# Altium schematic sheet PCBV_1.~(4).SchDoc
size A4; SheetNumber: 1; SheetTotal: 1
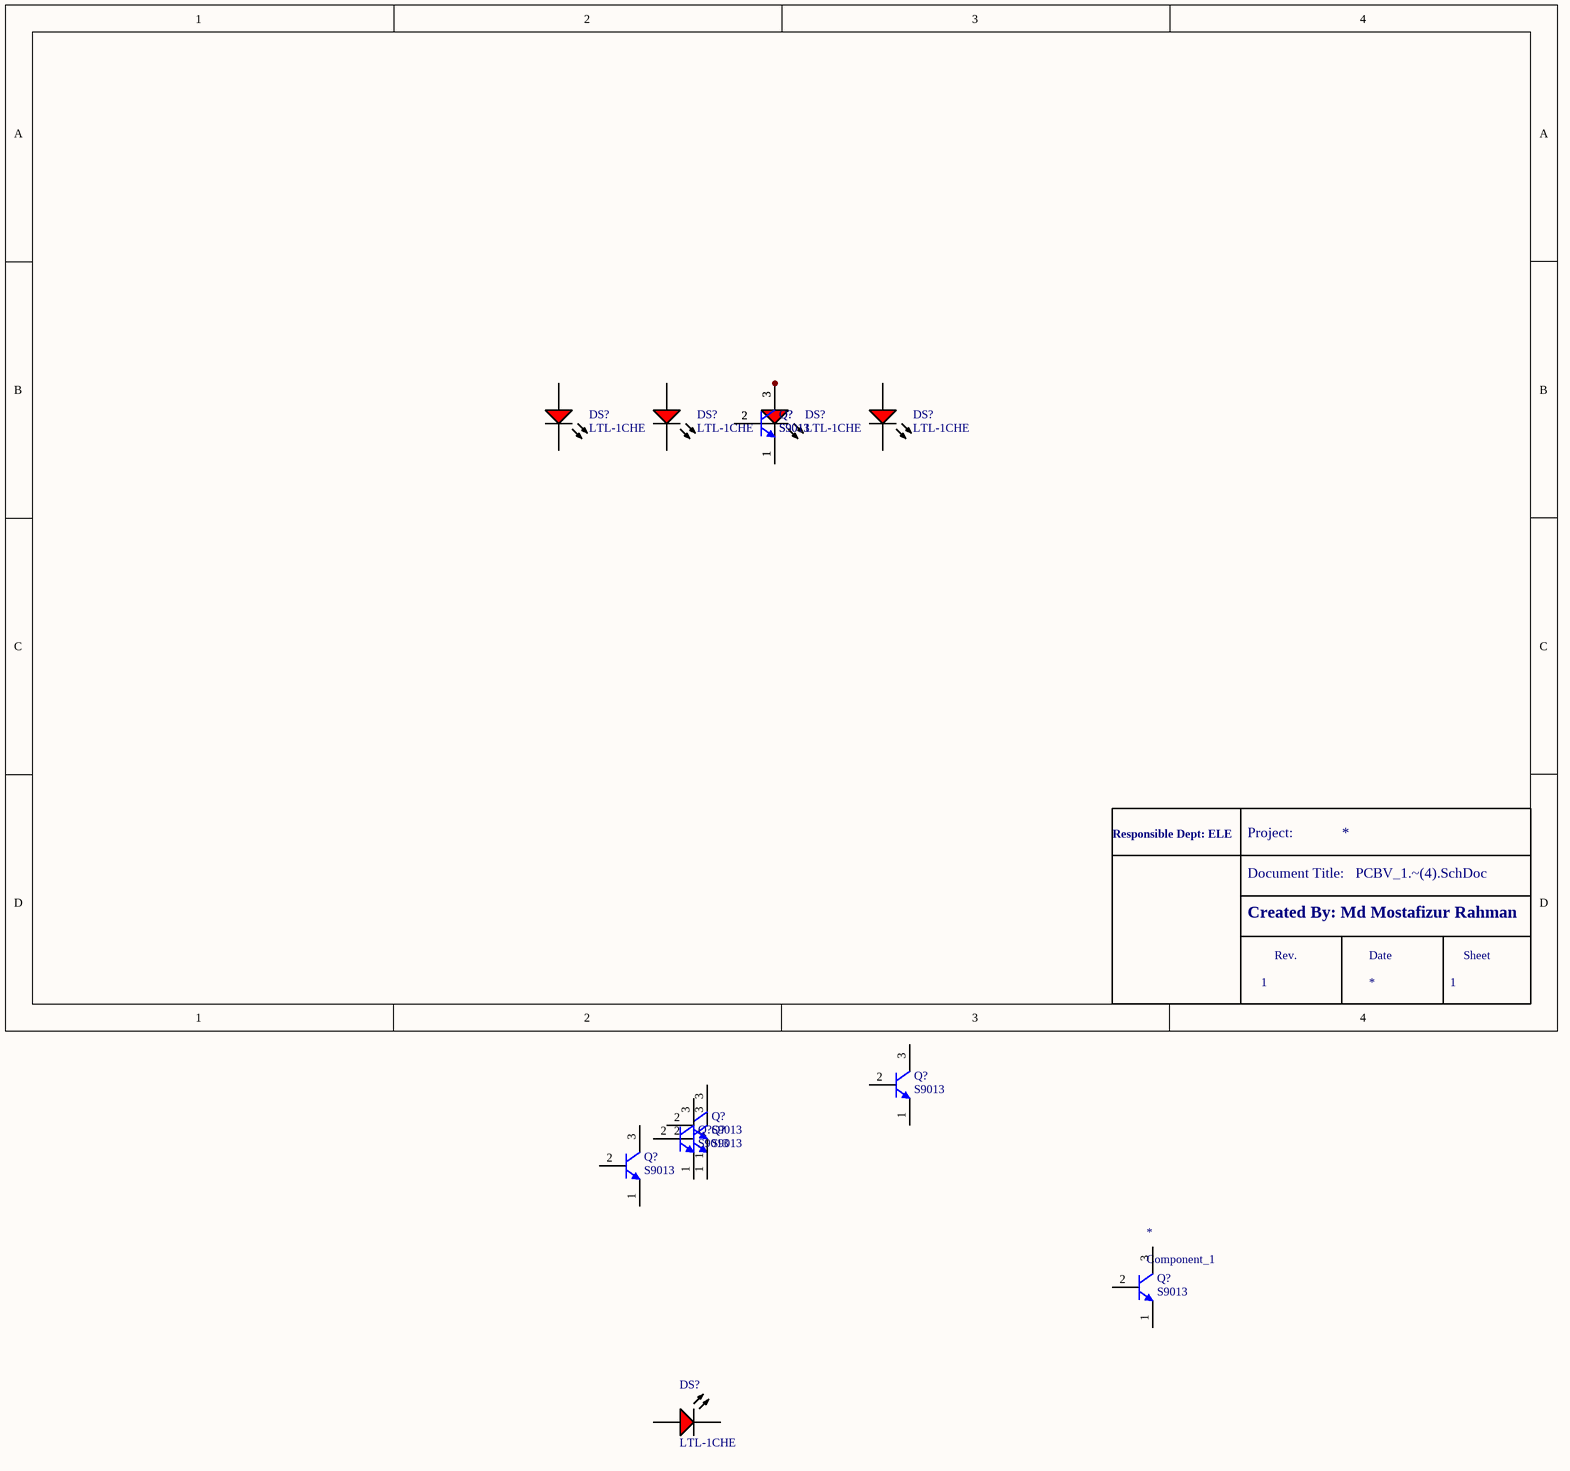
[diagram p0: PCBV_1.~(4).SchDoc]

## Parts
(Parts that share a designator on the sheet are numbered #1, #2 ... from top to bottom, then left to right.)
*#1  HSHL Title Block  (value not drawn)  (graphical)
*#2  Component_1
DS?#1  LTL-1CHE  [INDPR60-254-520X380X650]
DS?#2  LTL-1CHE  [INDPR60-254-520X380X650]
DS?#3  LTL-1CHE  [INDPR60-254-520X380X650]
DS?#4  LTL-1CHE  [INDPR60-254-520X380X650]
DS?#5  LTL-1CHE  [INDPR60-254-520X380X650]
Q?#1  S9013  [JSCJ-TO-92-3_V]
Q?#2  S9013  [JSCJ-TO-92-3_V]
Q?#3  S9013  [JSCJ-TO-92-3_V]
Q?#4  S9013  [JSCJ-TO-92-3_V]
Q?#5  S9013  [JSCJ-TO-92-3_V]
Q?#6  S9013  [JSCJ-TO-92-3_V]
Q?#7  S9013  [JSCJ-TO-92-3_V]
Q?#8  S9013  [JSCJ-TO-92-3_V]

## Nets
NetDS?#3_1: DS?#3.1(A) Q?#1.3(C) Q?#2.3(C)
NetQ?#1_1: Q?#1.1(E) Q?#2.1(E)
NetQ?#1_2: Q?#1.2(B) Q?#2.2(B)

Not connected (* = marked no-connect by the designer): DS?#1 1(A) 2(K); DS?#2 1(A) 2(K); DS?#3 2(K); DS?#4 1(A) 2(K); DS?#5 1(A) 2(K); Q?#3 1(E) 2(B) 3(C); Q?#4 1(E) 2(B) 3(C); Q?#5 1(E) 2(B) 3(C); Q?#6 1(E) 2(B) 3(C); Q?#7 1(E) 2(B) 3(C); Q?#8 1(E) 2(B) 3(C)

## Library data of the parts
DS?#1-DS?#5 = CMP-007-00018-2: LED Uni-Color Red, 100 mW, 30 mA, -55 to 100 degC, 2-Pin THD, RoHS, Bulk; Manufacturer: Lite-On; Forward Current: 20mA; Nominal Vf: 2V; Viewing Angle: 60degrees; Luminous Intensity: 12.6mcd; Lens Style: Dome
Q?#1-Q?#8 = CMP-013-00000-3: Transistor, NPN, 0.1 uA, 150 MHz, 3-Pin TO-92; Manufacturer: Jiangsu Changjiang Electronics Technology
